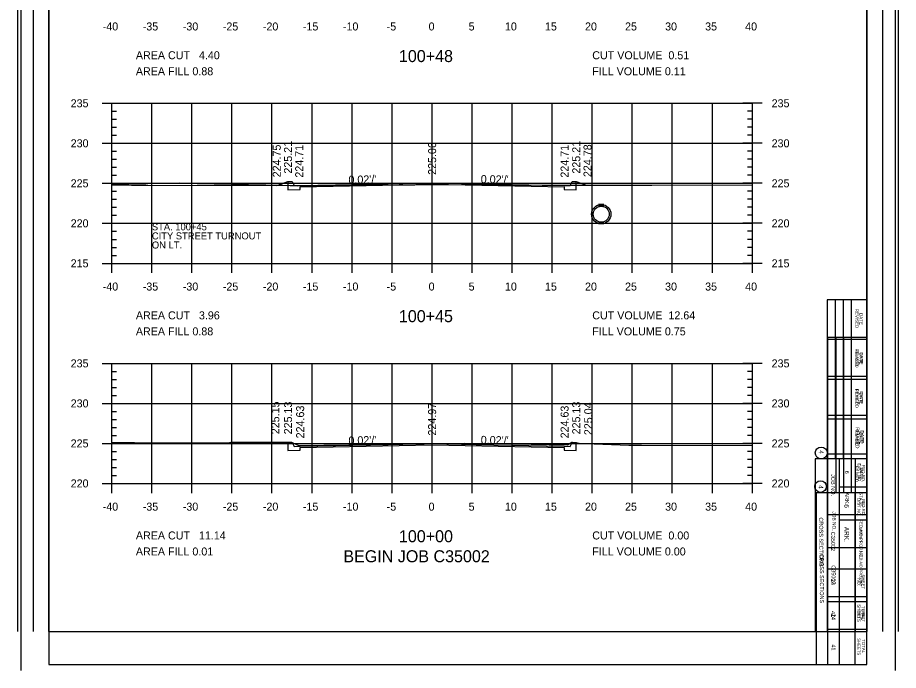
# Model space of a CAD drawing. Extents: x 1367903 to 1373764, y 376865 to 382130.
# Drawn here: x 1369499.9 to 1369719.9, y 377279.1 to 377442.3 of the extents above; entities that cross this region are included whole.
import ezdxf

# ---------------------------------------------------------------- set-up
doc = ezdxf.new("R2010")
doc.units = 0
for name, color, linetype in [('R_Axis', 7, 'Continuous'), ('R_Axis Annot', 7, 'Continuous'), ('R_Border', 7, 'Continuous'), ('R_Border Notes', 7, 'Continuous'), ('R_Border PE', 7, 'Continuous'), ('R_Draft', 7, 'Continuous'), ('R_Drive', 7, 'Continuous'), ('R_Exist Surface', 7, 'Continuous'), ('R_Fin Surface', 7, 'Continuous'), ('R_Fin Surface Annot', 7, 'Continuous'), ('R_Grid', 7, 'Continuous'), ('R_Water', 7, 'Continuous')]:
    doc.layers.add(name, color=color, linetype=linetype)

msp = doc.modelspace()

# ---------------------------------------------------------------- linework, layer by layer
for points in [[(1369567.46, 377401.26), (1369567.46, 377400.59), (1369567.46, 377400.59), (1369567.46, 377399.23), (1369570.46, 377399.29), (1369570.46, 377399.96), (1369603.46, 377400.62), (1369636.46, 377399.96), (1369636.46, 377399.29), (1369639.46, 377399.23), (1369639.46, 377401.26)], [(1369567.46, 377336.1), (1369567.46, 377335.43), (1369567.46, 377335.43), (1369567.46, 377334.07), (1369570.46, 377334.13), (1369570.46, 377334.79), (1369603.46, 377335.45), (1369636.46, 377334.79), (1369636.46, 377334.13), (1369639.46, 377334.07), (1369639.46, 377336.1)]]:
    msp.add_lwpolyline(points)
at = {"layer": 'R_Axis'}
for p, q in [((1369521.06, 377420.84), (1369525.86, 377420.84)), ((1369523.46, 377380.84), (1369523.46, 377420.84)), ((1369685.86, 377420.84), (1369681.06, 377420.84)), ((1369683.46, 377380.84), (1369683.46, 377420.84)), ((1369523.46, 377418.84), (1369524.66, 377418.84)), ((1369683.46, 377418.84), (1369682.26, 377418.84)), ((1369523.46, 377416.84), (1369524.66, 377416.84)), ((1369683.46, 377416.84), (1369682.26, 377416.84)), ((1369523.46, 377414.84), (1369524.66, 377414.84)), ((1369523.46, 377412.84), (1369524.66, 377412.84)), ((1369683.46, 377414.84), (1369682.26, 377414.84)), ((1369683.46, 377412.84), (1369682.26, 377412.84)), ((1369521.06, 377410.84), (1369525.86, 377410.84)), ((1369685.86, 377410.84), (1369681.06, 377410.84)), ((1369523.46, 377408.84), (1369524.66, 377408.84)), ((1369683.46, 377408.84), (1369682.26, 377408.84)), ((1369523.46, 377406.84), (1369524.66, 377406.84)), ((1369683.46, 377406.84), (1369682.26, 377406.84)), ((1369523.46, 377404.84), (1369524.66, 377404.84)), ((1369683.46, 377404.84), (1369682.26, 377404.84)), ((1369523.46, 377402.84), (1369524.66, 377402.84)), ((1369683.46, 377402.84), (1369682.26, 377402.84)), ((1369521.06, 377400.84), (1369525.86, 377400.84)), ((1369685.86, 377400.84), (1369681.06, 377400.84)), ((1369523.46, 377398.84), (1369524.66, 377398.84)), ((1369683.46, 377398.84), (1369682.26, 377398.84)), ((1369523.46, 377396.84), (1369524.66, 377396.84)), ((1369683.46, 377396.84), (1369682.26, 377396.84)), ((1369523.46, 377394.84), (1369524.66, 377394.84)), ((1369683.46, 377394.84), (1369682.26, 377394.84)), ((1369521.06, 377390.84), (1369525.86, 377390.84)), ((1369523.46, 377392.84), (1369524.66, 377392.84)), ((1369685.86, 377390.84), (1369681.06, 377390.84)), ((1369683.46, 377392.84), (1369682.26, 377392.84)), ((1369523.46, 377388.84), (1369524.66, 377388.84)), ((1369683.46, 377388.84), (1369682.26, 377388.84)), ((1369523.46, 377386.84), (1369524.66, 377386.84)), ((1369683.46, 377386.84), (1369682.26, 377386.84)), ((1369523.46, 377384.84), (1369524.66, 377384.84)), ((1369683.46, 377384.84), (1369682.26, 377384.84)), ((1369523.46, 377378.44), (1369523.46, 377383.24)), ((1369523.46, 377382.84), (1369524.66, 377382.84)), ((1369533.46, 377378.44), (1369533.46, 377383.24)), ((1369543.46, 377378.44), (1369543.46, 377383.24)), ((1369553.46, 377378.44), (1369553.46, 377383.24)), ((1369563.46, 377378.44), (1369563.46, 377383.24)), ((1369573.46, 377378.44), (1369573.46, 377383.24)), ((1369583.46, 377378.44), (1369583.46, 377383.24)), ((1369593.46, 377378.44), (1369593.46, 377383.24)), ((1369603.46, 377378.44), (1369603.46, 377383.24)), ((1369613.46, 377378.44), (1369613.46, 377383.24)), ((1369623.46, 377378.44), (1369623.46, 377383.24)), ((1369633.46, 377378.44), (1369633.46, 377383.24)), ((1369643.46, 377378.44), (1369643.46, 377383.24)), ((1369653.46, 377378.44), (1369653.46, 377383.24)), ((1369663.46, 377378.44), (1369663.46, 377383.24)), ((1369673.46, 377378.44), (1369673.46, 377383.24)), ((1369683.46, 377382.84), (1369682.26, 377382.84)), ((1369683.46, 377378.44), (1369683.46, 377383.24)), ((1369521.06, 377380.84), (1369525.86, 377380.84)), ((1369523.46, 377380.84), (1369683.46, 377380.84)), ((1369685.86, 377380.84), (1369681.06, 377380.84)), ((1369521.06, 377355.84), (1369525.86, 377355.84)), ((1369523.46, 377325.84), (1369523.46, 377355.84)), ((1369685.86, 377355.84), (1369681.06, 377355.84)), ((1369683.46, 377325.84), (1369683.46, 377355.84)), ((1369523.46, 377353.84), (1369524.66, 377353.84)), ((1369683.46, 377353.84), (1369682.26, 377353.84)), ((1369523.46, 377351.84), (1369524.66, 377351.84)), ((1369683.46, 377351.84), (1369682.26, 377351.84)), ((1369523.46, 377349.84), (1369524.66, 377349.84)), ((1369683.46, 377349.84), (1369682.26, 377349.84)), ((1369523.46, 377347.84), (1369524.66, 377347.84)), ((1369683.46, 377347.84), (1369682.26, 377347.84)), ((1369521.06, 377345.84), (1369525.86, 377345.84)), ((1369685.86, 377345.84), (1369681.06, 377345.84)), ((1369523.46, 377343.84), (1369524.66, 377343.84)), ((1369683.46, 377343.84), (1369682.26, 377343.84)), ((1369523.46, 377341.84), (1369524.66, 377341.84)), ((1369683.46, 377341.84), (1369682.26, 377341.84)), ((1369523.46, 377339.84), (1369524.66, 377339.84)), ((1369683.46, 377339.84), (1369682.26, 377339.84)), ((1369521.06, 377335.84), (1369525.86, 377335.84)), ((1369523.46, 377337.84), (1369524.66, 377337.84)), ((1369685.86, 377335.84), (1369681.06, 377335.84)), ((1369683.46, 377337.84), (1369682.26, 377337.84)), ((1369523.46, 377333.84), (1369524.66, 377333.84)), ((1369683.46, 377333.84), (1369682.26, 377333.84)), ((1369523.46, 377331.84), (1369524.66, 377331.84)), ((1369683.46, 377331.84), (1369682.26, 377331.84)), ((1369523.46, 377329.84), (1369524.66, 377329.84)), ((1369683.46, 377329.84), (1369682.26, 377329.84)), ((1369523.46, 377323.44), (1369523.46, 377328.24)), ((1369523.46, 377327.84), (1369524.66, 377327.84)), ((1369533.46, 377323.44), (1369533.46, 377328.24)), ((1369543.46, 377323.44), (1369543.46, 377328.24)), ((1369553.46, 377323.44), (1369553.46, 377328.24)), ((1369563.46, 377323.44), (1369563.46, 377328.24)), ((1369573.46, 377323.44), (1369573.46, 377328.24)), ((1369583.46, 377323.44), (1369583.46, 377328.24)), ((1369593.46, 377323.44), (1369593.46, 377328.24)), ((1369603.46, 377323.44), (1369603.46, 377328.24)), ((1369613.46, 377323.44), (1369613.46, 377328.24)), ((1369623.46, 377323.44), (1369623.46, 377328.24)), ((1369633.46, 377323.44), (1369633.46, 377328.24)), ((1369643.46, 377323.44), (1369643.46, 377328.24)), ((1369653.46, 377323.44), (1369653.46, 377328.24)), ((1369663.46, 377323.44), (1369663.46, 377328.24)), ((1369673.46, 377323.44), (1369673.46, 377328.24)), ((1369683.46, 377327.84), (1369682.26, 377327.84)), ((1369683.46, 377323.44), (1369683.46, 377328.24)), ((1369521.06, 377325.84), (1369525.86, 377325.84)), ((1369523.46, 377325.84), (1369683.46, 377325.84)), ((1369685.86, 377325.84), (1369681.06, 377325.84))]:
    msp.add_line(p, q, dxfattribs=at)
at = {"layer": 'R_Border'}
for p, q in [((1369500.73, 377620.35), (1369500.73, 377279.12)), ((1369719.12, 377620.35), (1369719.12, 377279.12)), ((1369507.76, 377611.47), (1369507.76, 377280.59)), ((1369712.08, 377280.59), (1369712.08, 377611.47)), ((1369702.27, 377280.59), (1369702.27, 377362.43)), ((1369702.27, 377362.43), (1369712.08, 377362.43)), ((1369702.27, 377362.43), (1369704.31, 377362.43)), ((1369704.31, 377362.43), (1369704.31, 377323.46)), ((1369706.25, 377362.43), (1369706.25, 377323.46)), ((1369708.1, 377362.43), (1369708.1, 377323.46)), ((1369702.27, 377352.62), (1369711.89, 377352.62)), ((1369702.27, 377342.9), (1369711.89, 377342.9)), ((1369702.27, 377333.27), (1369711.89, 377333.27)), ((1369712.08, 377323.46), (1369699.35, 377323.46)), ((1369699.35, 377323.46), (1369699.35, 377280.59)), ((1369705.19, 377280.59), (1369705.19, 377323.46)), ((1369709.17, 377280.59), (1369709.17, 377323.46)), ((1369712.08, 377316.65), (1369705.19, 377316.65)), ((1369712.08, 377309.75), (1369702.27, 377309.75)), ((1369712.08, 377296.24), (1369702.27, 377296.24)), ((1369712.08, 377289.33), (1369702.27, 377289.33)), ((1369507.76, 377280.59), (1369712.08, 377280.59))]:
    msp.add_line(p, q, dxfattribs=at)
msp.add_circle((1369700.49, 377325.07), 1.46, dxfattribs=at)
at = {"layer": 'R_Border PE'}
for p, q in [((1369499.92, 377610.76), (1369499.92, 377288.8)), ((1369503.84, 377610.76), (1369503.84, 377288.8)), ((1369716.01, 377288.8), (1369716.01, 377610.76)), ((1369719.92, 377288.8), (1369719.92, 377610.76)), ((1369507.76, 377288.8), (1369507.76, 377603.25)), ((1369712.08, 377603.25), (1369712.08, 377288.8)), ((1369702.14, 377371.74), (1369702.14, 377288.8)), ((1369712.08, 377371.74), (1369702.14, 377371.74)), ((1369704.13, 377371.74), (1369704.13, 377331.96)), ((1369706.11, 377371.74), (1369706.11, 377331.96)), ((1369708.1, 377371.74), (1369708.1, 377331.96)), ((1369712.08, 377361.8), (1369702.14, 377361.8)), ((1369712.08, 377351.85), (1369702.14, 377351.85)), ((1369712.08, 377341.91), (1369702.14, 377341.91)), ((1369712.08, 377331.96), (1369699.15, 377331.96)), ((1369699.15, 377331.96), (1369699.15, 377288.8)), ((1369705.12, 377331.96), (1369705.12, 377288.8)), ((1369709.1, 377331.96), (1369709.1, 377288.8)), ((1369705.18, 377325), (1369712.08, 377325)), ((1369702.27, 377318.04), (1369712.08, 377318.04)), ((1369702.27, 377304.51), (1369712.08, 377304.51)), ((1369702.27, 377297.55), (1369712.08, 377297.55)), ((1369507.76, 377288.8), (1369712.08, 377288.8)), ((1369709.19, 377288.8), (1369709.19, 377288.8))]:
    msp.add_line(p, q, dxfattribs=at)
msp.add_circle((1369700.64, 377333.45), 1.49, dxfattribs=at)
at = {"layer": 'R_Drive'}
for q in [(1369523.46, 377400.52), (1369570.46, 377400.29)]:
    msp.add_line((1369540.46, 377400.89), q, dxfattribs=at)
at = {"layer": 'R_Exist Surface'}
for points in [[(1369523.46, 377400.44), (1369528.38, 377400.41), (1369531.36, 377400.39), (1369532.2, 377400.4), (1369532.46, 377400.39), (1369568.04, 377400.33), (1369568.13, 377400.33), (1369568.41, 377400.32), (1369569.86, 377400.23), (1369586.35, 377400.38), (1369611.97, 377400.52), (1369630.93, 377400.39), (1369637.88, 377400.38), (1369638.42, 377400.41), (1369639.17, 377400.4), (1369658.36, 377400.41), (1369683.46, 377400.42)], [(1369523.46, 377336.19), (1369529.08, 377336.07), (1369543.32, 377336.02), (1369552.09, 377335.98), (1369552.81, 377336.06), (1369553.15, 377336.16), (1369559.92, 377336.19), (1369562.83, 377336.18), (1369564.14, 377336.15), (1369568.32, 377336.12), (1369568.87, 377335.89), (1369570.17, 377335.31), (1369601.48, 377335.76), (1369611.63, 377335.88), (1369619.02, 377335.78), (1369637.25, 377335.5), (1369638.38, 377336.13), (1369638.46, 377336.18), (1369638.5, 377336.11), (1369638.73, 377335.97), (1369641.78, 377335.82), (1369652.62, 377335.42), (1369653.57, 377335.42), (1369655.78, 377335.41), (1369683.46, 377335.3)]]:
    msp.add_lwpolyline(points, dxfattribs=at)
at = {"layer": 'R_Fin Surface'}
for points in [[(1369564.65, 377400.33), (1369567.46, 377401.26), (1369568.46, 377401.26), (1369568.96, 377400.26), (1369570.46, 377400.29), (1369592.46, 377400.73), (1369603.46, 377400.95), (1369614.46, 377400.73), (1369636.46, 377400.29), (1369637.96, 377400.26), (1369638.46, 377401.26), (1369639.46, 377401.26), (1369642.03, 377400.4)], [(1369567.34, 377336.13), (1369567.46, 377336.1), (1369568.46, 377336.1), (1369568.96, 377335.1), (1369570.46, 377335.13), (1369592.46, 377335.57), (1369603.46, 377335.79), (1369614.46, 377335.57), (1369636.46, 377335.13), (1369637.96, 377335.1), (1369638.46, 377336.1), (1369639.46, 377336.1), (1369640.02, 377335.91)]]:
    msp.add_lwpolyline(points, dxfattribs=at)
at = {"layer": 'R_Grid'}
for p, q in [((1369523.46, 377420.84), (1369683.46, 377420.84)), ((1369523.46, 377380.84), (1369523.46, 377420.84)), ((1369533.46, 377380.84), (1369533.46, 377420.84)), ((1369543.46, 377380.84), (1369543.46, 377420.84)), ((1369553.46, 377380.84), (1369553.46, 377420.84)), ((1369563.46, 377380.84), (1369563.46, 377420.84)), ((1369573.46, 377380.84), (1369573.46, 377420.84)), ((1369583.46, 377380.84), (1369583.46, 377420.84)), ((1369593.46, 377380.84), (1369593.46, 377420.84)), ((1369603.46, 377380.84), (1369603.46, 377420.84)), ((1369613.46, 377380.84), (1369613.46, 377420.84)), ((1369623.46, 377380.84), (1369623.46, 377420.84)), ((1369633.46, 377380.84), (1369633.46, 377420.84)), ((1369643.46, 377380.84), (1369643.46, 377420.84)), ((1369653.46, 377380.84), (1369653.46, 377420.84)), ((1369663.46, 377380.84), (1369663.46, 377420.84)), ((1369673.46, 377380.84), (1369673.46, 377420.84)), ((1369683.46, 377380.84), (1369683.46, 377420.84)), ((1369523.46, 377410.84), (1369683.46, 377410.84)), ((1369523.46, 377400.84), (1369683.46, 377400.84)), ((1369523.46, 377390.84), (1369683.46, 377390.84)), ((1369523.46, 377380.84), (1369683.46, 377380.84)), ((1369523.46, 377355.84), (1369683.46, 377355.84)), ((1369523.46, 377325.84), (1369523.46, 377355.84)), ((1369533.46, 377325.84), (1369533.46, 377355.84)), ((1369543.46, 377325.84), (1369543.46, 377355.84)), ((1369553.46, 377325.84), (1369553.46, 377355.84)), ((1369563.46, 377325.84), (1369563.46, 377355.84)), ((1369573.46, 377325.84), (1369573.46, 377355.84)), ((1369583.46, 377325.84), (1369583.46, 377355.84)), ((1369593.46, 377325.84), (1369593.46, 377355.84)), ((1369603.46, 377325.84), (1369603.46, 377355.84)), ((1369613.46, 377325.84), (1369613.46, 377355.84)), ((1369623.46, 377325.84), (1369623.46, 377355.84)), ((1369633.46, 377325.84), (1369633.46, 377355.84)), ((1369643.46, 377325.84), (1369643.46, 377355.84)), ((1369653.46, 377325.84), (1369653.46, 377355.84)), ((1369663.46, 377325.84), (1369663.46, 377355.84)), ((1369673.46, 377325.84), (1369673.46, 377355.84)), ((1369683.46, 377325.84), (1369683.46, 377355.84)), ((1369523.46, 377345.84), (1369683.46, 377345.84)), ((1369523.46, 377335.84), (1369683.46, 377335.84)), ((1369523.46, 377325.84), (1369683.46, 377325.84))]:
    msp.add_line(p, q, dxfattribs=at)
at = {"layer": 'R_Water'}
for p, q in [((1369646.35, 377395.56), (1369645.04, 377395.51)), ((1369646.35, 377395.14), (1369645.04, 377395.09)), ((1369646.35, 377391.14), (1369645.04, 377391.09)), ((1369646.35, 377390.73), (1369645.04, 377390.68))]:
    msp.add_line(p, q, dxfattribs=at)
for radius in [2.42, 2]:
    msp.add_circle((1369645.7, 377393.12), radius, dxfattribs=at)

# ---------------------------------------------------------------- texts
at = {"layer": 'R_Axis Annot'}
for s, height, p in [('-40', 2, (1369521.18, 377439.04)), ('-35', 2, (1369531.18, 377439.04)), ('-30', 2, (1369541.18, 377439.04)), ('-25', 2, (1369551.18, 377439.04)), ('-20', 2, (1369561.18, 377439.04)), ('-15', 2, (1369571.18, 377439.04)), ('-10', 2, (1369581.18, 377439.04)), ('-5', 2, (1369592.11, 377439.04)), ('0', 2, (1369602.58, 377439.04)), ('5', 2, (1369612.58, 377439.04)), ('10', 2, (1369621.65, 377439.04)), ('15', 2, (1369631.65, 377439.04)), ('20', 2, (1369641.65, 377439.04)), ('25', 2, (1369651.65, 377439.04)), ('30', 2, (1369661.65, 377439.04)), ('35', 2, (1369671.65, 377439.04)), ('40', 2, (1369681.65, 377439.04)), ('AREA CUT   4.40', 2, (1369529.46, 377431.84)), ('100+48', 3, (1369595.17, 377431.14)), ('CUT VOLUME  0.51', 2, (1369643.46, 377431.84)), ('AREA FILL 0.88', 2, (1369529.46, 377427.84)), ('FILL VOLUME 0.11', 2, (1369643.46, 377427.84)), ('235', 2, (1369513.17, 377419.84)), ('235', 2, (1369688.26, 377419.84)), ('230', 2, (1369513.18, 377409.84)), ('230', 2, (1369688.26, 377409.84)), ('225', 2, (1369513.17, 377399.84)), ('225', 2, (1369688.26, 377399.84)), ('220', 2, (1369513.18, 377389.84)), ('220', 2, (1369688.26, 377389.84)), ('215', 2, (1369513.17, 377379.84)), ('215', 2, (1369688.26, 377379.84)), ('-40', 2, (1369521.18, 377374.04)), ('-35', 2, (1369531.18, 377374.04)), ('-30', 2, (1369541.18, 377374.04)), ('-25', 2, (1369551.18, 377374.04)), ('-20', 2, (1369561.18, 377374.04)), ('-15', 2, (1369571.18, 377374.04)), ('-10', 2, (1369581.18, 377374.04)), ('-5', 2, (1369592.11, 377374.04)), ('0', 2, (1369602.58, 377374.04)), ('5', 2, (1369612.58, 377374.04)), ('10', 2, (1369621.65, 377374.04)), ('15', 2, (1369631.65, 377374.04)), ('20', 2, (1369641.65, 377374.04)), ('25', 2, (1369651.65, 377374.04)), ('30', 2, (1369661.65, 377374.04)), ('35', 2, (1369671.65, 377374.04)), ('40', 2, (1369681.65, 377374.04)), ('AREA CUT   3.96', 2, (1369529.46, 377366.84)), ('100+45', 3, (1369595.16, 377366.14)), ('CUT VOLUME  12.64', 2, (1369643.46, 377366.84)), ('AREA FILL 0.88', 2, (1369529.46, 377362.84)), ('FILL VOLUME 0.75', 2, (1369643.46, 377362.84)), ('235', 2, (1369513.17, 377354.84)), ('235', 2, (1369688.26, 377354.84)), ('230', 2, (1369513.18, 377344.84)), ('230', 2, (1369688.26, 377344.84)), ('225', 2, (1369513.17, 377334.84)), ('225', 2, (1369688.26, 377334.84)), ('220', 2, (1369513.18, 377324.84)), ('220', 2, (1369688.26, 377324.84)), ('-40', 2, (1369521.18, 377319.04)), ('-35', 2, (1369531.18, 377319.04)), ('-30', 2, (1369541.18, 377319.04)), ('-25', 2, (1369551.18, 377319.04)), ('-20', 2, (1369561.18, 377319.04)), ('-15', 2, (1369571.18, 377319.04)), ('-10', 2, (1369581.18, 377319.04)), ('-5', 2, (1369592.11, 377319.04)), ('0', 2, (1369602.58, 377319.04)), ('5', 2, (1369612.58, 377319.04)), ('10', 2, (1369621.65, 377319.04)), ('15', 2, (1369631.65, 377319.04)), ('20', 2, (1369641.65, 377319.04)), ('25', 2, (1369651.65, 377319.04)), ('30', 2, (1369661.65, 377319.04)), ('35', 2, (1369671.65, 377319.04)), ('40', 2, (1369681.65, 377319.04)), ('AREA CUT   11.14', 2, (1369529.46, 377311.84)), ('100+00', 3, (1369595.17, 377311.14)), ('CUT VOLUME  0.00', 2, (1369643.46, 377311.84)), ('AREA FILL 0.01', 2, (1369529.46, 377307.84)), ('FILL VOLUME 0.00', 2, (1369643.46, 377307.84)), ('BEGIN JOB C35002', 3, (1369581.29, 377306.14))]:
    msp.add_text(s, height=height, dxfattribs=at).set_placement(p)
at = {"layer": 'R_Border'}
for s, height, p in [('REVISED', 0.778, (1369709.17, 377359.51)), ('DATE', 0.778, (1369710.33, 377358.64)), ('FILMED', 0.778, (1369709.17, 377349.41)), ('DATE', 0.778, (1369710.33, 377348.82)), ('REVISED', 0.875, (1369709.27, 377339.88)), ('DATE', 0.875, (1369710.43, 377339.1)), ('FILMED', 0.778, (1369709.17, 377330.16)), ('DATE', 0.778, (1369710.33, 377329.77)), ('4', 1.17, (1369699.98, 377325.4)), ('6', 1.17, (1369706.44, 377320.63)), ('DIST.NO.', 0.778, (1369709.66, 377322.19)), ('FED.RD.', 0.778, (1369710.82, 377321.99)), ('JOB NO.', 0.875, (1369703.44, 377318.88)), ('ARK.', 1.166, (1369706.44, 377315)), ('STATE', 0.681, (1369710.14, 377314.9)), ('FED.AID PROJ.NO.', 0.6805, (1369710.24, 377308.49)), ('SHEET', 0.681, (1369710.82, 377294.39)), ('NO.', 0.681, (1369709.66, 377293.61)), ('SHEETS', 0.778, (1369709.66, 377287.2)), ('TOTAL', 0.778, (1369710.82, 377286.91))]:
    msp.add_text(s, height=height, rotation=270, dxfattribs=at).set_placement(p)
at = {"layer": 'R_Border Notes'}
for s, height, p in [('CROSS SECTIONS', 0.9945, (1369700.31, 377308.2)), ('C35002', 0.995, (1369703.23, 377305.39)), ('24', 0.995, (1369703.23, 377293.25)), ('41', 0.995, (1369703.23, 377285.62))]:
    msp.add_text(s, height=height, rotation=270, dxfattribs=at).set_placement(p)
at = {"layer": 'R_Border PE'}
for s, height, p in [('REVISED', 0.796, (1369709.18, 377369.47)), ('DATE', 0.796, (1369710.21, 377368.41)), ('FILMED', 0.796, (1369709.18, 377359.12)), ('DATE', 0.796, (1369710.21, 377358.47)), ('REVISED', 0.796, (1369709.18, 377349.57)), ('DATE', 0.796, (1369710.21, 377348.52)), ('FILMED', 0.796, (1369709.18, 377339.23)), ('DATE', 0.796, (1369710.21, 377338.58)), ('4', 1.19, (1369700.05, 377334.12)), ('DIST.NO.', 0.796, (1369709.75, 377330.83)), ('FED.RD.', 0.796, (1369710.78, 377330.52)), ('JOB NO.', 0.995, (1369703.13, 377328.19)), ('6', 0.995, (1369706.61, 377329.02)), ('ARK.', 0.995, (1369706.61, 377323.6)), ('STATE', 0.796, (1369710.19, 377323.66)), ('CROSS SECTIONS', 0.9945, (1369700.15, 377317.35)), ('FED.AID PROJ.NO.', 0.7956, (1369710.19, 377316.88)), ('C35002', 0.995, (1369703.13, 377313.75)), ('SHEET', 0.796, (1369710.71, 377303.09)), ('24', 0.995, (1369703.13, 377301.98)), ('NO.', 0.796, (1369709.68, 377302.11)), ('SHEETS', 0.796, (1369709.68, 377295.62)), ('TOTAL', 0.796, (1369710.71, 377295.23)), ('41', 0.995, (1369703.13, 377293.96))]:
    msp.add_text(s, height=height, rotation=270, dxfattribs=at).set_placement(p)
at = {"layer": 'R_Draft'}
for s, p in [('STA. 100+45', (1369533.46, 377389.09)), ('CITY STREET TURNOUT', (1369533.46, 377386.82)), ('ON LT.', (1369533.46, 377384.55))]:
    msp.add_text(s, height=1.75, dxfattribs=at).set_placement(p)
at = {"layer": 'R_Fin Surface Annot'}
for s, rotation, p in [('225.21', 90, (1369568.46, 377403.26)), ('225.06', 90, (1369604.46, 377402.95)), ('225.21', 90, (1369640.46, 377403.26)), ('224.75', 90, (1369565.65, 377402.33)), ('224.71', 90, (1369571.26, 377402.26)), ('224.71', 90, (1369637.54, 377402.26)), ('224.78', 90, (1369643.28, 377402.4)), ("0.02'/'", 1.1458, (1369582.58, 377400.73)), ("0.02'/'", 358.8542, (1369615.59, 377400.91)), ('225.15', 90, (1369565.3, 377338.13)), ('225.13', 90, (1369568.46, 377338.1)), ('224.63', 90, (1369571.5, 377337.1)), ('224.97', 90, (1369604.46, 377337.79)), ('224.63', 90, (1369637.55, 377337.1)), ('225.13', 90, (1369640.46, 377338.1)), ('225.04', 90, (1369643.46, 377337.91)), ("0.02'/'", 1.1458, (1369582.58, 377335.57)), ("0.02'/'", 358.8542, (1369615.59, 377335.74))]:
    msp.add_text(s, height=2, rotation=rotation, dxfattribs=at).set_placement(p)

doc.saveas('drawing.dxf')
